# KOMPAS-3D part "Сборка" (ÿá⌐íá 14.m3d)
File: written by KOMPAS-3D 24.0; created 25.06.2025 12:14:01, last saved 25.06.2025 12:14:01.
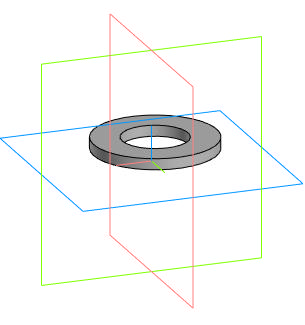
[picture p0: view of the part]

Document properties: Автор: PC321; Полное имя файла: C:\Для ноута\Инженерная графика\ППЭ 2025-2026\Варианты 1-38\Вариант 11 СБ\Вар 11 СБ\Шайба 14.m3d

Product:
- Component [standard]: Шайба A.14.37 ГОСТ 11371-78  | qty 1  | pos. 1  | Материал: АД1 ГОСТ 4784-97 (density 1000 kg/m3); Масса: 0.008612; Раздел спецификации: Стандартные изделия; Рассекать на разрезах: no
- Part/product: Сборка
    Масса: 0.008612

Referenced files in C:\Program Files\ASCON\KOMPAS-3D v21 Study\Libs\PARTLib\DATA\vault\Methods\Kompas\3D\: PLib_Washer_1_712.m3d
